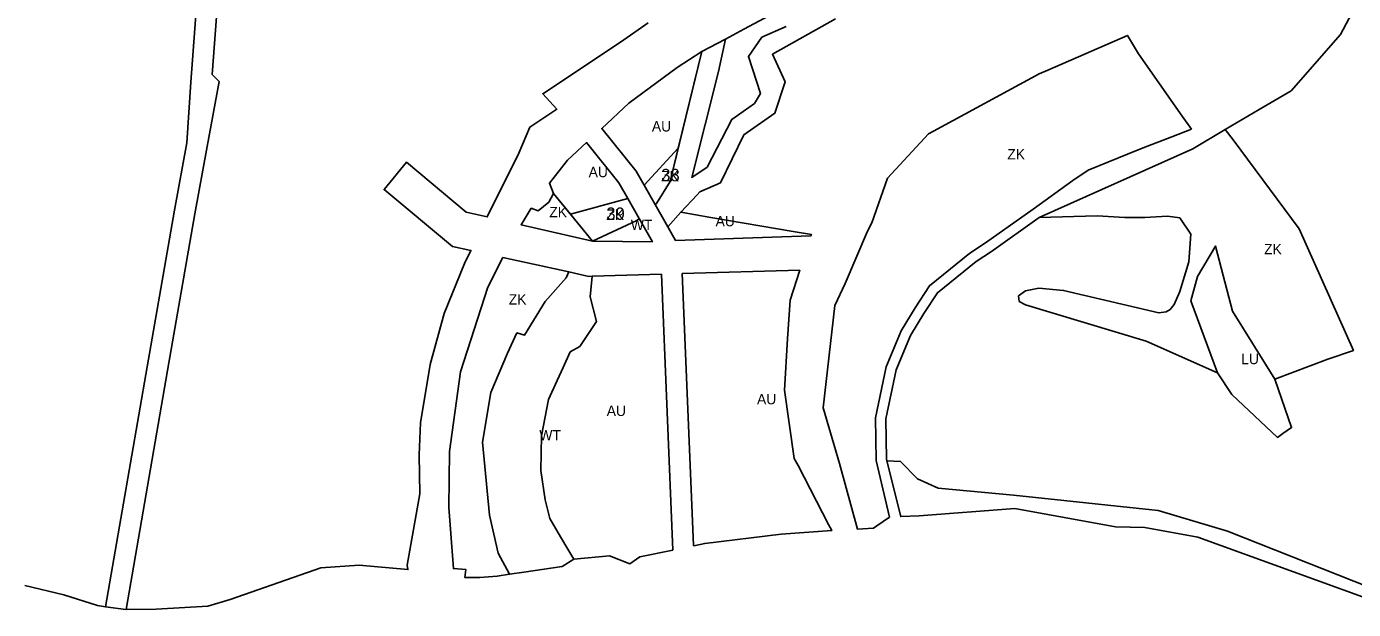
# Model space of a CAD drawing. Extents: x -521261 to -517465, y -1182764 to -1179456.
# Drawn here: x -519568 to -518928, y -1182349 to -1182068 of the extents above; entities that cross this region are included whole.
import ezdxf

# ---------------------------------------------------------------- set-up
doc = ezdxf.new("R2010")
doc.units = 0
for name, color, linetype in [('90640013', 7, 'Continuous'), ('90710013', 7, 'Continuous'), ('90710023', 7, 'Continuous'), ('90750013', 7, 'Continuous'), ('90770013', 7, 'Continuous'), ('ID_navrh', 7, 'Continuous')]:
    doc.layers.add(name, color=color, linetype=linetype)

msp = doc.modelspace()

# ---------------------------------------------------------------- linework, layer by layer
at = {"layer": '90640013'}
msp.add_lwpolyline([(-519178.02, -1182063.84), (-519208.47, -1182080.89), (-519202.24, -1182094.17), (-519207.36, -1182109.41), (-519222.19, -1182119.81), (-519233.52, -1182143.05), (-519243.51, -1182147.35), (-519244.72, -1182148.81), (-519252.66, -1182157.13), (-519258.995, -1182164.197), (-519265.048, -1182153.515), (-519264.43, -1182152.98), (-519257.87, -1182142.38), (-519242.46, -1182079.64), (-519231.14, -1182073.63), (-519234.48, -1182089.27), (-519247.35, -1182140.4), (-519240.01, -1182135.46), (-519228.11, -1182112.41), (-519217.04, -1182104.65), (-519214.26, -1182099.83), (-519220.07, -1182082.09), (-519213.54, -1182072.66), (-519201.77, -1182067.5)], dxfattribs=at)
for points in [[(-519272.759, -1182160.191), (-519272.759, -1182160.191), (-519266.376, -1182171.455), (-519295.34, -1182171.1), (-519273.82, -1182161.11)], [(-519306.72, -1182186.025), (-519297.063, -1182188.147), (-519295.481, -1182188.101), (-519296.44, -1182198.05), (-519293.39, -1182209.86), (-519301.4, -1182222.05), (-519305.97, -1182224.59), (-519309.39, -1182232.07), (-519312.28, -1182238.35), (-519316.52, -1182247.61), (-519319.88, -1182265.09), (-519320.28, -1182281.86), (-519318.16, -1182296.06), (-519315.87, -1182305.01), (-519310.74, -1182313.8), (-519307.19, -1182319.84), (-519304.31, -1182324.69), (-519309.87, -1182328.17), (-519328.47, -1182330.84), (-519335.25, -1182331.89), (-519340.84, -1182321.8), (-519345.01, -1182303.33), (-519348.42, -1182268.22), (-519344.33, -1182244.15), (-519336.36, -1182225.28), (-519331.74, -1182215.45), (-519328.11, -1182216.56), (-519318.07, -1182200.28), (-519307.99, -1182188.78)]]:
    msp.add_lwpolyline(points, close=True, dxfattribs=at)
at = {"layer": '90710013'}
for points in [[(-519201.77, -1182067.5), (-519213.54, -1182072.66), (-519220.07, -1182082.09), (-519214.26, -1182099.83), (-519217.04, -1182104.65), (-519228.11, -1182112.41), (-519240.01, -1182135.46), (-519247.35, -1182140.4), (-519234.48, -1182089.27), (-519231.14, -1182073.63), (-519222.3, -1182068.89), (-519199.92, -1182056.85)], [(-518910.86, -1182347.51), (-519003.18, -1182314), (-519028.78, -1182309.33), (-519042.89, -1182309.05), (-519091.46, -1182300.2), (-519137.73, -1182303.79), (-519146.55, -1182304.08), (-519153.235, -1182277.183), (-519146.65, -1182277.49), (-519138.39, -1182285.89), (-519128.43, -1182290.37), (-519092.07, -1182293.82), (-519022.28, -1182301.22), (-518988.83, -1182311.11), (-518904.79, -1182344.46)]]:
    msp.add_lwpolyline(points, dxfattribs=at)
for points in [[(-519006.27, -1182117.14), (-519015.68, -1182120.79), (-519029.51, -1182126.07), (-519037.12, -1182129.21), (-519056.16, -1182136.93), (-519063.58, -1182141.86), (-519082.7, -1182155.73), (-519105.61, -1182172.01), (-519113.15, -1182176.92), (-519132.61, -1182192.66), (-519139.61, -1182203.31), (-519146.38, -1182214.41), (-519153.61, -1182231.85), (-519158.67, -1182256.49), (-519158.44, -1182276.94), (-519151.97, -1182304.35), (-519158.09, -1182308.61), (-519159.7, -1182309.74), (-519167.38, -1182310.17), (-519176.17, -1182278.4), (-519184.01, -1182251.52), (-519178.27, -1182202.24), (-519173.29, -1182191.64), (-519162.51, -1182166.28), (-519160.42, -1182162.23), (-519152.93, -1182140.79), (-519133.19, -1182119.37), (-519130.79, -1182118.09), (-519079.71, -1182090.45), (-519075.61, -1182088.64), (-519037.14, -1182071.87), (-519031.78, -1182080.78), (-519010.79, -1182110.87)], [(-518993.75, -1182234.73), (-519028.21, -1182219.45), (-519086.34, -1182201.94), (-519089.45, -1182200.22), (-519089.76, -1182197.58), (-519086.34, -1182195.09), (-519079.97, -1182193.85), (-519068, -1182194.94), (-519021.98, -1182205.82), (-519018.56, -1182205.2), (-519016.54, -1182204.11), (-519014.67, -1182201.78), (-519011.87, -1182195.4), (-519007.49, -1182181.05), (-519006.56, -1182167.72), (-519011.928, -1182159.818), (-519017.78, -1182159.16), (-519028.82, -1182159.79), (-519038.46, -1182159.79), (-519051.83, -1182158.85), (-519079.784, -1182159.792), (-519005.58, -1182126.593), (-518989.945, -1182117.266), (-518989.945, -1182117.266), (-518986.196, -1182122.308), (-518954.27, -1182165.24), (-518928.17, -1182223.92), (-518940.53, -1182228.04), (-518966.08, -1182237.71), (-518986.47, -1182204.96), (-518994.67, -1182173.52), (-519003.38, -1182188.28), (-519006.59, -1182199.98)], [(-519295.34, -1182171.1), (-519329.751, -1182163.186), (-519324.83, -1182155.25), (-519321.46, -1182156.51), (-519316.32, -1182152.28), (-519314.14, -1182148.07)], [(-519338.56, -1182179.026), (-519306.72, -1182186.025), (-519307.99, -1182188.78), (-519318.07, -1182200.28), (-519328.11, -1182216.56), (-519331.74, -1182215.45), (-519336.36, -1182225.28), (-519344.33, -1182244.15), (-519348.42, -1182268.22), (-519345.01, -1182303.33), (-519340.84, -1182321.8), (-519335.25, -1182331.89), (-519341.35, -1182332.84), (-519349.57, -1182333.44), (-519356.83, -1182333.54), (-519356.45, -1182329.61), (-519362.36, -1182329.2), (-519364.66, -1182299.65), (-519364.33, -1182272.7), (-519359.04, -1182234.21), (-519345.85, -1182193.35)]]:
    msp.add_lwpolyline(points, close=True, dxfattribs=at)
at = {"layer": '90710023'}
msp.add_lwpolyline([(-519467.21, -1181936.45), (-519478.73, -1182090.66), (-519475.35, -1182094.14), (-519481.13, -1182125.46), (-519487.14, -1182158), (-519500.27, -1182233.5), (-519520.343, -1182348.919), (-519520.37, -1182348.92), (-519530.261, -1182347.588), (-519510.122, -1182231.787), (-519496.983, -1182156.235), (-519490.964, -1182123.644), (-519489.037, -1182094.401), (-519477.42, -1181938.895)], dxfattribs=at)
for points in [[(-519265.048, -1182153.515), (-519270.348, -1182144.162), (-519253.913, -1182126.268), (-519257.87, -1182142.38), (-519264.43, -1182152.98)], [(-519305.921, -1182158.139), (-519278.18, -1182150.625), (-519272.759, -1182160.191), (-519272.759, -1182160.191), (-519273.82, -1182161.11), (-519295.34, -1182171.1)]]:
    msp.add_lwpolyline(points, close=True, dxfattribs=at)
at = {"layer": '90750013'}
for points in [[(-519572.226, -1181713.022), (-519551.44, -1181777.767), (-519542.674, -1181815.764), (-519537.803, -1181819.937), (-519532.962, -1181835.589), (-519526.127, -1181857.622), (-519517.13, -1181872.903), (-519496.468, -1181907.457), (-519477.42, -1181938.895), (-519489.037, -1182094.401), (-519490.964, -1182123.644), (-519496.983, -1182156.235), (-519510.122, -1182231.787), (-519530.261, -1182347.588), (-519534.18, -1182347.06), (-519550.42, -1182341.81), (-519569.087, -1182337.379)], [(-519268.355, -1182065.839), (-519281.77, -1182075.133), (-519319.308, -1182099.962), (-519312.519, -1182107.461), (-519325.55, -1182116.08), (-519330.82, -1182128.68), (-519346.065, -1182159.434), (-519356.198, -1182157.104), (-519385.094, -1182133.074), (-519395.814, -1182146.27), (-519362.843, -1182173.688), (-519353.952, -1182175.642), (-519356.97, -1182181.87), (-519366.78, -1182206.14), (-519373.61, -1182230.65), (-519378.32, -1182258.87), (-519378.89, -1182274.23), (-519378.51, -1182293.11), (-519384.76, -1182327.55), (-519384.34, -1182329.69), (-519407.79, -1182327.6), (-519426.27, -1182328.75), (-519470.15, -1182344.05), (-519480.86, -1182347.27), (-519505.85, -1182348.7), (-519520.343, -1182348.919), (-519500.27, -1182233.5), (-519487.14, -1182158), (-519481.13, -1182125.46), (-519475.35, -1182094.14), (-519478.73, -1182090.66), (-519467.21, -1181936.45)], [(-518904.79, -1182344.46), (-518988.83, -1182311.11), (-519022.28, -1182301.22), (-519092.07, -1182293.82), (-519128.43, -1182290.37), (-519138.39, -1182285.89), (-519146.65, -1182277.49), (-519153.235, -1182277.183), (-519153.446, -1182276.33), (-519153.664, -1182256.97), (-519148.808, -1182233.324), (-519141.909, -1182216.683), (-519135.385, -1182205.986), (-519128.86, -1182196.057), (-519110.206, -1182180.969), (-519102.797, -1182176.144), (-519079.784, -1182159.792), (-519051.83, -1182158.85), (-519038.46, -1182159.79), (-519028.82, -1182159.79), (-519017.78, -1182159.16), (-519011.928, -1182159.818), (-519006.56, -1182167.72), (-519007.49, -1182181.05), (-519011.87, -1182195.4), (-519014.67, -1182201.78), (-519016.54, -1182204.11), (-519018.56, -1182205.2), (-519021.98, -1182205.82), (-519068, -1182194.94), (-519079.97, -1182193.85), (-519086.34, -1182195.09), (-519089.76, -1182197.58), (-519089.45, -1182200.22), (-519086.34, -1182201.94), (-519028.21, -1182219.45), (-518993.75, -1182234.73), (-518986.74, -1182245.15), (-518964.8, -1182265.87), (-518962.22, -1182263.91), (-518957.97, -1182261.15), (-518966.08, -1182237.71), (-518940.53, -1182228.04), (-518928.17, -1182223.92), (-518954.27, -1182165.24), (-518986.196, -1182122.308), (-518989.945, -1182117.266), (-518989.945, -1182117.266), (-518973.625, -1182107.53), (-518958.234, -1182098.605), (-518934.385, -1182071.457), (-518925.034, -1182053.763)]]:
    msp.add_lwpolyline(points, dxfattribs=at)
for points in [[(-519253.913, -1182126.268), (-519270.348, -1182144.162), (-519274.231, -1182137.31), (-519290.782, -1182116.703), (-519277.73, -1182104.52), (-519254.35, -1182087.3), (-519242.46, -1182079.64)], [(-519278.18, -1182150.625), (-519305.921, -1182158.139), (-519314.14, -1182148.07), (-519316.09, -1182143.16), (-519307.3, -1182132.12), (-519298.113, -1182123.545), (-519282.533, -1182142.943)], [(-519255.258, -1182170.792), (-519258.995, -1182164.197), (-519252.66, -1182157.13), (-519238.23, -1182159.7), (-519198.46, -1182166.41), (-519189.658, -1182167.895), (-519189.658, -1182167.895), (-519189.857, -1182168.509)], [(-519261.956, -1182187.123), (-519256.526, -1182320.234), (-519272.44, -1182323.5), (-519277.18, -1182326.84), (-519287.11, -1182323.04), (-519304.31, -1182324.69), (-519307.19, -1182319.84), (-519310.74, -1182313.8), (-519315.87, -1182305.01), (-519318.16, -1182296.06), (-519320.28, -1182281.86), (-519319.88, -1182265.09), (-519316.52, -1182247.61), (-519312.28, -1182238.35), (-519309.39, -1182232.07), (-519305.97, -1182224.59), (-519301.4, -1182222.05), (-519293.39, -1182209.86), (-519296.44, -1182198.05), (-519295.481, -1182188.101)], [(-519246.432, -1182318.162), (-519246.615, -1182317.83), (-519251.96, -1182186.831), (-519195.277, -1182185.177), (-519199.96, -1182199.58), (-519201.12, -1182218.25), (-519202.63, -1182243.03), (-519197.91, -1182276), (-519196.1, -1182279.49), (-519181.38, -1182307.96), (-519179.83, -1182310.84), (-519204.17, -1182312.58), (-519241.11, -1182317.07)]]:
    msp.add_lwpolyline(points, close=True, dxfattribs=at)
at = {"layer": '90770013'}
msp.add_lwpolyline([(-518957.97, -1182261.15), (-518962.22, -1182263.91), (-518964.8, -1182265.87), (-518986.74, -1182245.15), (-518993.75, -1182234.73), (-519006.59, -1182199.98), (-519003.38, -1182188.28), (-518994.67, -1182173.52), (-518986.47, -1182204.96), (-518966.08, -1182237.71)], close=True, dxfattribs=at)

# ---------------------------------------------------------------- texts
at = {"layer": '90640013'}
for rotation, p in [(360, (-519276.77, -1182165.823)), (0, (-519320.905, -1182267.316))]:
    msp.add_text('WT', height=5, rotation=rotation, dxfattribs=at).set_placement(p)
at = {"layer": '90710013'}
for rotation, p in [(0, (-519095.14, -1182131.685)), (360, (-519316.129, -1182159.585)), (0, (-518971.229, -1182177.488)), (360, (-519335.69, -1182201.756))]:
    msp.add_text('ZK', height=5, rotation=rotation, dxfattribs=at).set_placement(p)
at = {"layer": '90710023'}
for p in [(-519262.13, -1182142.24), (-519288.616, -1182160.863)]:
    msp.add_text('ZK', height=5, rotation=0, dxfattribs=at).set_placement(p)
at = {"layer": '90750013'}
for rotation, p in [(0, (-519266.621, -1182118.221)), (0, (-519297.135, -1182140.261)), (360, (-519235.879, -1182163.961)), (360, (-519215.895, -1182249.892)), (360, (-519288.403, -1182255.529))]:
    msp.add_text('AU', height=5, rotation=rotation, dxfattribs=at).set_placement(p)
at = {"layer": '90770013'}
msp.add_text('LU', height=5, rotation=360, dxfattribs=at).set_placement((-518982.28, -1182230.526))
at = {"layer": 'ID_navrh'}
for s, rotation, p in [('38', 0, (-519262.13, -1182142.24)), ('39', 360, (-519288.616, -1182160.863))]:
    msp.add_text(s, height=6, rotation=rotation, dxfattribs=at).set_placement(p)

doc.saveas('drawing.dxf')
